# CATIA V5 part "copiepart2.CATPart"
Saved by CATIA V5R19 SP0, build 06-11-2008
Part number: Part2
Bounding box of the stored display mesh (mm): x -14 to 14, y -13.97 to 13.97, z -6 to 52
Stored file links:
  G:\EU_thinkMotion\CFAO_2010\SIL_groupe2\SIL_groupe2\A reprendre\vfouquet\fouquet\copiepart2.CATPart
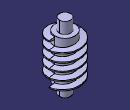
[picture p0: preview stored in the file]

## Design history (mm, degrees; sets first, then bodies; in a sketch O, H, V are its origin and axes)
Body1 (main body)
  Point1: (0, 0, 0)
  Point2: (10, 0, 0)
  Line1: type PtDir, RefPoint Point1, Direction xy-plane, Start 0, End 20
  Helix1: Direction Line1, RefPoint Point2, Pitch 7, Height 35, TaperAngle 0
  Sketch1 on yz-plane, origin (0, 0, 0), H (0, 1, 0), V (0, 0, 1)
    line L1 (0, 40) -> (-5, 40)
    line L2 (-5, 40) -> (-14, 39)
    line L3 (-14, 39) -> (-14, 38)
    line L4 (-14, 38) -> (-5, 37)
    line L5 (0, 40) -> (-5, 37)
  Rib1: profile Sketch1, centre curve Helix1
  Sketch2 on xy-plane, origin (0, 0, 0), H (1, 0, 0), V (0, 1, 0)
    circle A1 centre (0, 0) radius 9
    radius A1 = 9
  Pad1: profile Sketch2, direction (0, 0, 1), length 42, opposite side length -4
  Sketch3 on xy-plane, origin (0, 0, 0), H (1, 0, 0), V (0, 1, 0)
    circle A1 centre (0, 0) radius 5
    radius A1 = 5
  Pad2: profile Sketch3, direction (0, 0, 1), length 52, opposite side length 6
